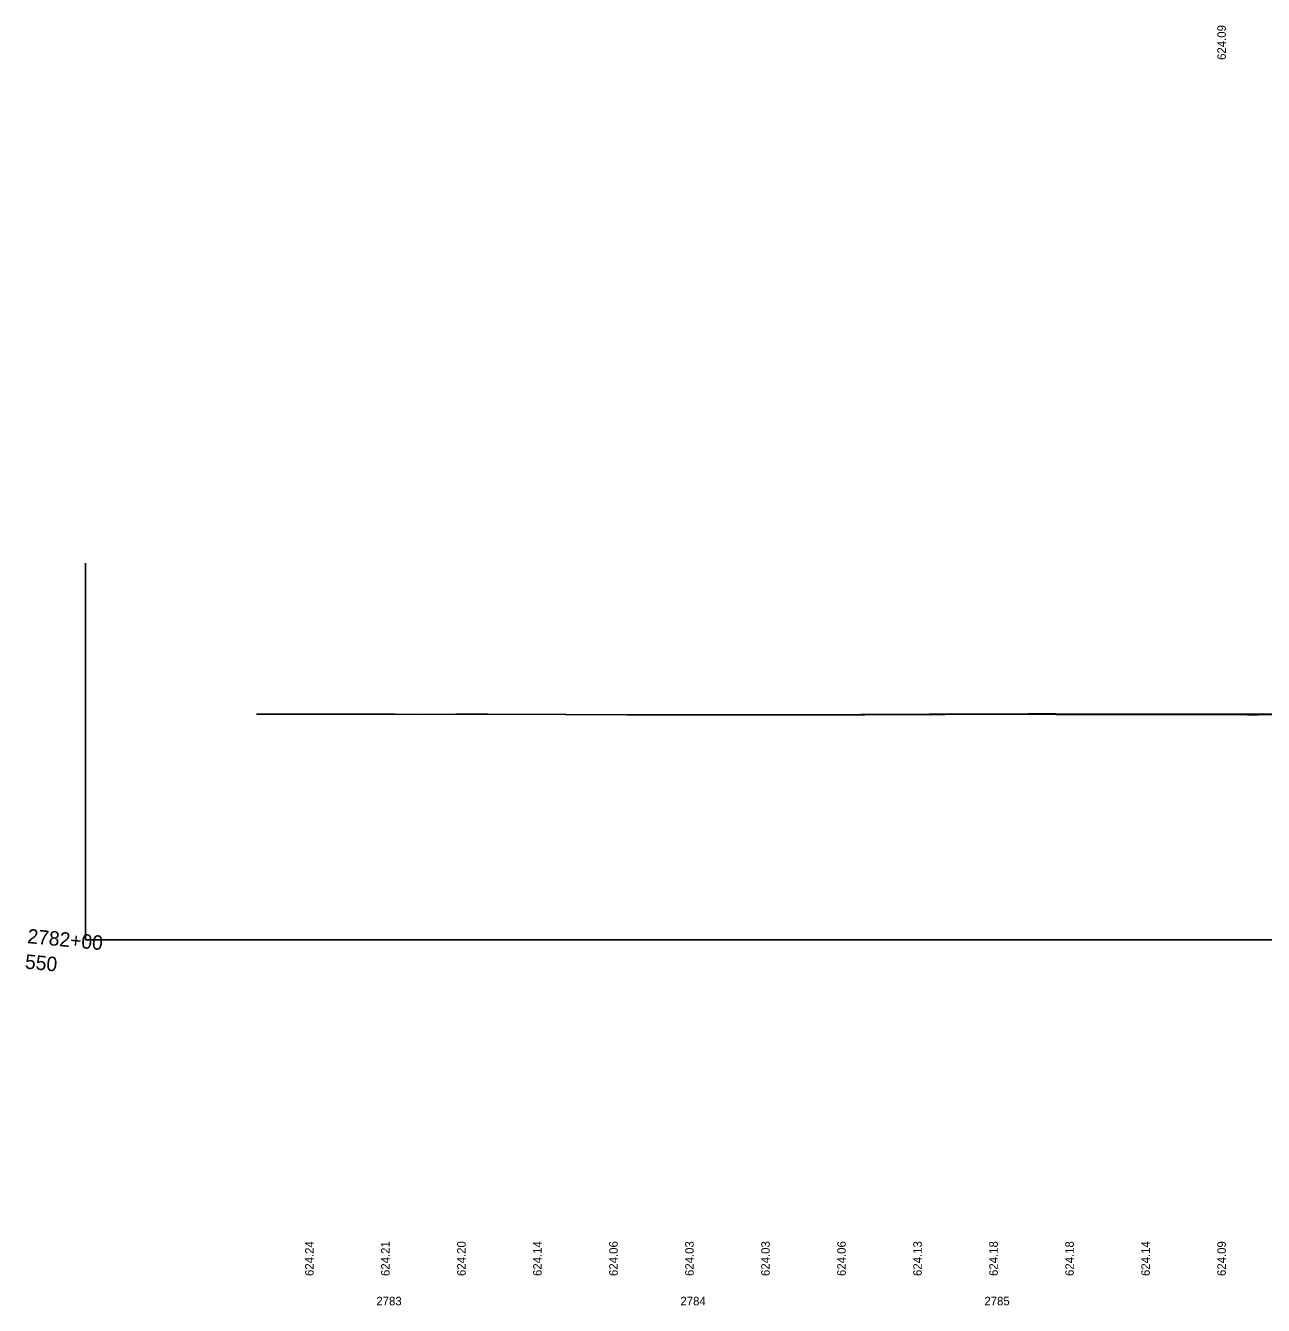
# Model space of a CAD drawing. Extents: x 2376379 to 2383101, y 559608 to 561720.
# Drawn here: x 2378745.9 to 2379153, y 559608.2 to 560029.2 of the extents above; entities that cross this region are included whole.
import ezdxf

# ---------------------------------------------------------------- set-up
doc = ezdxf.new("R2010")
doc.units = 0
for name, color, linetype in [('BR_X_SV_Shot_Marker', 7, 'Continuous'), ('DR_X_Erosion_Control', 7, 'Continuous'), ('PV_X_Driveway', 7, 'Continuous'), ('SV_X_Text', 7, 'Continuous'), ('UT_X_Overhead_Electric', 7, 'Continuous')]:
    doc.layers.add(name, color=color, linetype=linetype)

msp = doc.modelspace()

# ---------------------------------------------------------------- linework, layer by layer
at = {"layer": 'PV_X_Driveway'}
msp.add_lwpolyline([(2378821.82, 559802.72), (2378837.3, 559802.7), (2378838.23, 559802.7), (2378848.64, 559802.71), (2378866.33, 559802.67), (2378867.27, 559802.67), (2378874.29, 559802.65), (2378887.41, 559802.67), (2378888.39, 559802.67), (2378897.96, 559802.66), (2378923.33, 559802.57), (2378923.72, 559802.57), (2378943.66, 559802.51), (2378944.75, 559802.51), (2378948.87, 559802.5), (2378950.02, 559802.5), (2378974.48, 559802.49), (2378986.38, 559802.49), (2378987.94, 559802.49), (2378999.17, 559802.49), (2379020.64, 559802.53), (2379021.89, 559802.53), (2379046.54, 559802.61), (2379047.66, 559802.62), (2379048.26, 559802.62), (2379075.73, 559802.66), (2379076.3, 559802.66), (2379084.76, 559802.65), (2379099.25, 559802.63), (2379124.24, 559802.59), (2379125.8, 559802.59), (2379138.93, 559802.56), (2379147.75, 559802.54), (2379151.22, 559802.54), (2379175.95, 559802.56)], dxfattribs=at)
at = {"layer": 'SV_X_Text'}
for p, q in [((2378765.62, 559852.41), (2378765.62, 559728.46)), ((2378765.62, 559728.46), (2380329.61, 559728.46))]:
    msp.add_line(p, q, dxfattribs=at)
at = {"layer": 'UT_X_Overhead_Electric'}
for points in [[(2379043.12, 559802.73), (2379021.9, 559802.6), (2379020.64, 559802.6), (2378999.18, 559802.51), (2378990.62, 559802.49)], [(2379193.12, 559802.69), (2379175.95, 559802.69), (2379151.22, 559802.67), (2379147.75, 559802.66), (2379138.93, 559802.68), (2379124.24, 559802.71), (2379099.25, 559802.76), (2379084.76, 559802.78), (2379075.73, 559802.79), (2379048.26, 559802.74), (2379046.54, 559802.74), (2379043.12, 559802.73)]]:
    msp.add_lwpolyline(points, dxfattribs=at)

# ---------------------------------------------------------------- texts
at = {"layer": 'BR_X_SV_Shot_Marker'}
for s, p in [('624.24', (2378840.62, 559617.89)), ('624.21', (2378865.62, 559617.89)), ('624.20', (2378890.62, 559617.89)), ('624.14', (2378915.62, 559617.89)), ('624.06', (2378940.62, 559617.89)), ('624.03', (2378965.62, 559617.89)), ('624.03', (2378990.62, 559617.89)), ('624.06', (2379015.62, 559617.89)), ('624.13', (2379040.62, 559617.89)), ('624.18', (2379065.62, 559617.89)), ('624.18', (2379090.62, 559617.89)), ('624.14', (2379115.62, 559617.89)), ('624.09', (2379140.62, 559617.89))]:
    msp.add_text(s, height=2.8, rotation=90, dxfattribs=at).set_placement(p)
for s, p in [('2783', (2378861.25, 559608.25)), ('2784', (2378961.24, 559608.25)), ('2785', (2379061.21, 559608.25))]:
    msp.add_text(s, height=2.8, dxfattribs=at).set_placement(p)
at = {"layer": 'DR_X_Erosion_Control'}
msp.add_text('624.09', height=2.8, rotation=90, dxfattribs=at).set_placement((2379140.62, 560017.95))
at = {"layer": 'SV_X_Text'}
for s, p in [('2782+00', (2378746.34, 559727.41)), ('550', (2378745.55, 559719.04))]:
    msp.add_text(s, height=4.737, rotation=354.583, dxfattribs=at).set_placement(p)

doc.saveas('drawing.dxf')
